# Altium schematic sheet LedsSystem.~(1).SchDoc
size A4
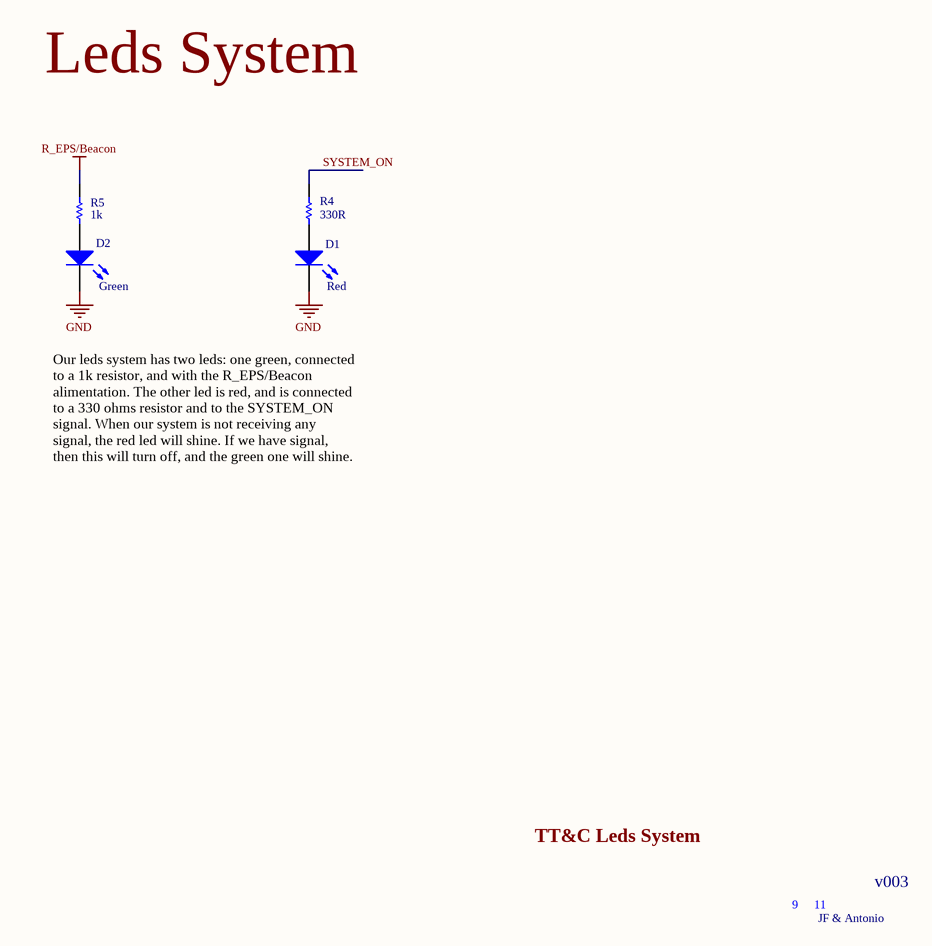
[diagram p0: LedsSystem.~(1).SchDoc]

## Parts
D1  Red  [LEDR]
D2  Green  [LEDG]
R4  value 330R  [R330]
R5  1k  [R1k]

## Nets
GND: D1.2(K) D2.2(K)
R_EPS/Beacon: R5.2
SYSTEM_ON: R4.2

Not connected (* = marked no-connect by the designer): D1 1(A); D2 1(A); R4 1; R5 1

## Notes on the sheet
- Leds System
- Our leds system has two leds: one green, connected to a 1k resistor, and with the R_EPS/Beacon alimentation. The other led is red, and is connected to a 330 ohms resistor and to the SYSTEM_ON signal. When our system is not receiving any signal, the red led will shine. If we have signal, then this will turn off, and the green one will shine.
- TT&C Leds System
- 9
- 11
- v003
- JF & Antonio

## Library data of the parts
D1 D2 = LED2: Typical RED, GREEN, YELLOW, AMBER GaAs LED
R4 R5 = Res1: Resistor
